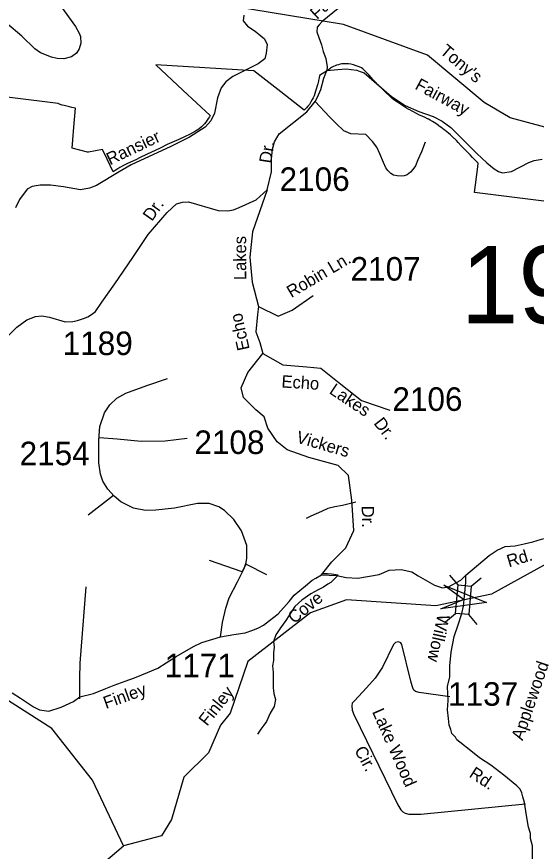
# Model space of a CAD drawing. Extents: x 884530 to 1028605, y 526725 to 653634.
# Drawn here: x 956415 to 959170, y 579851 to 584283 of the extents above; entities that cross this region are included whole.
import ezdxf

# ---------------------------------------------------------------- set-up
doc = ezdxf.new("R2010")
doc.units = 0
for name, color, linetype in [('Exist Boundary Political City Limit New', 7, 'Continuous'), ('Exist Hydrographic Creek Single Shore', 7, 'Continuous'), ('Exist Hydrographic Creek Single Shore Label', 7, 'Continuous'), ('Exist Hydrographic Misc Water Feature', 7, 'Continuous'), ('Exist Road Non-System Type 51', 7, 'Continuous'), ('Exist Road Non-System Type 51 Label', 7, 'Continuous'), ('Exist Road Secondary Structure Standard Bridge Attributed CELL', 7, 'Continuous'), ('Exist Road Secondary Structure Standard Bridge CELL', 7, 'Continuous'), ('Exist Road Secondary Structure Standard Bridge Number Label', 7, 'Continuous'), ('Exist Road Secondary Type 51 Attributed', 7, 'Continuous'), ('Exist Road Secondary Type 51 Label', 7, 'Continuous'), ('Exist Road Secondary Type 51 Number Label', 7, 'Continuous'), ('Map Preparation Boundary City Limit Buffer Line', 7, 'Continuous')]:
    doc.layers.add(name, color=color, linetype=linetype)

msp = doc.modelspace()

# ---------------------------------------------------------------- linework, layer by layer
at = {"layer": 'Exist Boundary Political City Limit New'}
for points in [[(958078.9, 584009.2), (958075.8, 584006.8), (958074.4, 584005.7), (958071.6, 584003.1), (958020.8, 583971.1), (958018.2, 583957.6), (958015.4, 583944.6), (958014.8, 583941.4), (958011.1, 583926.2), (957999.8, 583887.5), (957995.8, 583874.6), (957991.6, 583862.7), (957987.1, 583852.8), (957981.8, 583842.5), (957974.9, 583830.2), (957966.9, 583817.1), (957959.2, 583807.1), (957950.8, 583798.1), (957939, 583787.1), (957816.2, 583883.1), (957672.6, 583995.4), (957152.9, 584026.8), (957296.2, 583893.3), (957440.6, 583758.8), (957437.6, 583751.6), (957432.5, 583743.5), (957425.6, 583733.8), (957417.6, 583723.3), (957409.8, 583713.9), (957402.2, 583705.7), (957394.9, 583698.8), (957380.5, 583686.1), (957363.6, 583675.5), (957330.3, 583657.7), (957308.2, 583646.8), (957274.4, 583631.6), (957236.6, 583614.9), (957212.3, 583603.6), (957175.6, 583585.5), (957103.5, 583550.9), (957069.4, 583534.9), (957047.1, 583523.6), (957034.1, 583517.3), (956999.3, 583501.4), (956985.3, 583494.3), (956961.3, 583481.5), (956950.2, 583475.1), (956936.8, 583466.5), (956926.7, 583459.8), (956894, 583527), (956869.2, 583577.9), (956795.1, 583563.8), (956789.7, 583562.8), (956708.2, 583584.6), (956712.1, 583628.4), (956718, 583695.9), (956726.9, 583797.4), (956707.6, 583801.2), (956693.8, 583804.4), (956666.7, 583810.8), (956655.1, 583813.8), (956644.9, 583816.9), (956633.9, 583821.1), (955920.9, 583911.3)], [(958148.6, 584032.6), (958138.3, 584032), (958130.4, 584030.7), (958120.7, 584028.1), (958110, 584025), (958088.4, 584015.1), (958083.9, 584012.6), (958078.9, 584009.2)], [(961105.4, 583066.7), (958842.8, 583349.2), (958860.6, 583485.1), (958863, 583504.6), (958832.1, 583535.8), (958818.9, 583549.3), (958784.2, 583585.1), (958772.4, 583597.3), (958756.3, 583615), (958746.9, 583625), (958738.2, 583633.6), (958735.1, 583636.6), (958731.5, 583639.9), (958724, 583647.1), (958714.8, 583655.5), (958704.9, 583663.8), (958686.4, 583678.4), (958681.4, 583682.4), (958664.9, 583696.1), (958656.1, 583702.3), (958652.6, 583704.8), (958636.8, 583715.2), (958620.1, 583725.8), (958606.9, 583733.8), (958598.1, 583738.7), (958596.1, 583739.7), (958593.3, 583741.2), (958580.9, 583747.4), (958568.4, 583753.2), (958547.9, 583762.6), (958534.4, 583769.3), (958495.7, 583789.7), (958493.8, 583790.7), (958482.7, 583797.2), (958454.8, 583815.7), (958433.8, 583828.5), (958420.3, 583837.9), (958406.8, 583848.8), (958389.3, 583864.1), (958377.6, 583875.4), (958354.8, 583898.2), (958344, 583908.7), (958329.6, 583922.2), (958328.1, 583923.7), (958317.5, 583934.6), (958304.9, 583948.1), (958283.9, 583972), (958274.1, 583982.6), (958259, 583997.5), (958256.9, 583999.6), (958250.6, 584006.3), (958242.9, 584012.2), (958230.8, 584017.4), (958215.8, 584022.1), (958200.1, 584026.8), (958187.2, 584030.2), (958174.1, 584032.2), (958161.3, 584032.8), (958148.6, 584032.6)]]:
    msp.add_lwpolyline(points, dxfattribs=at)
at = {"layer": 'Exist Hydrographic Creek Single Shore'}
for points in [[(962595.4, 581173), (962571.5, 581284.8), (962503.2, 581512.8), (962414.3, 581897.2), (962368.7, 581972.4), (962207.5, 582192.9), (961744.5, 582879.2), (961617, 582987.1), (961505.9, 583064.7), (961336.7, 583108.1), (960713.9, 583186.3), (960566.8, 583274.5), (960148.7, 583287.6), (959704.9, 583646.6), (959288.3, 583677.7), (959032.2, 583745.2), (958893.2, 583826.8), (958593.5, 584078.9), (958148.8, 584242.1), (957369.3, 584369.4), (957205.1, 584441.6)], [(959310.4, 581426), (958932.1, 581217.6), (958637.9, 581154.6), (958163.4, 581186.7), (957973.4, 581117.9), (957639.8, 580859.1), (957546.9, 580585.3), (957494.7, 580520.7), (957431.2, 580374.3), (957301.6, 580245.7), (957235.4, 580020.6), (957182.4, 579933.1), (956980.5, 579881.3)]]:
    msp.add_lwpolyline(points, dxfattribs=at)
at = {"layer": 'Exist Hydrographic Misc Water Feature'}
for points in [[(956980.5, 579881.3), (956817.3, 580229.2), (956601.7, 580502.7), (956324.3, 580678.9), (956053.6, 581045.3), (955930.4, 581100.3)], [(956480.1, 579638.7), (956757, 579689), (956980.5, 579881.3)]]:
    msp.add_lwpolyline(points, dxfattribs=at)
at = {"layer": 'Exist Road Non-System Type 51'}
for p, q in [((956927.3, 581741.3), (956793.2, 581636.5)), ((957609.6, 581335.6), (957437, 581396.3)), ((957609.6, 581335.6), (957631.8, 581375.6)), ((957631.8, 581375.6), (957739, 581320.5))]:
    msp.add_line(p, q, dxfattribs=at)
for points in [[(956644, 584345.2), (956726.3, 584230.7), (956746.6, 584194.6), (956752.7, 584177.4), (956755.3, 584142.4), (956745.2, 584111.6), (956730.9, 584089.4), (956705, 584070.6), (956663.7, 584059.2), (956629.9, 584060), (956599.1, 584067.5), (956540, 584091.6), (956511.2, 584111.8), (956442, 584179.8), (956362.2, 584246.8), (956291.8, 584292.6)], [(958147.1, 584348.8), (958035.4, 584257.1), (958019.3, 584240.1), (958008.2, 584227.1), (958007.3, 584202.4), (958017.7, 584172.1), (958032, 584133), (958040.9, 584097.3), (958053.6, 584061.4), (958060.6, 584016.7), (958059.9, 583996.9)], [(958059.9, 583996.9), (958118.1, 584002.4), (958161.8, 584005.6), (958188.9, 584002.4), (958218.4, 583998.4), (958236.8, 583991.3), (958256.7, 583984.1), (958403.3, 583859.8), (958475.8, 583810.5), (958547, 583779.2), (958623.9, 583752.3), (958671.7, 583728.4), (958717.1, 583695), (958854.8, 583557), (958907.5, 583506.1), (958947.4, 583475.1), (958970.8, 583461.5), (958991.3, 583454.6), (959039.1, 583461.5), (959130.7, 583508.4), (959159.1, 583518.9), (959201.1, 583527.2)], [(958581.5, 583616.6), (958561.6, 583565.2), (958542.2, 583522), (958529.1, 583490.4), (958516.3, 583470.7), (958503.8, 583457.1), (958485.4, 583443.9), (958469.3, 583438.4), (958453.2, 583436.9), (958433.2, 583437.5), (958413.3, 583442.3), (958399.7, 583450.8), (958382.2, 583465.4), (958372.7, 583479.8), (958359.6, 583508.2), (958341.2, 583554.8), (958324.5, 583589.6), (958301.5, 583620.2), (958266.6, 583657.6), (958186.4, 583660.5), (958149.1, 583677.3), (958108.4, 583716), (958073.6, 583751.5), (957998, 583832.1)], [(956854.4, 582048.9), (956947.3, 582041.6), (957074.9, 582028.5), (957202.4, 582031.1), (957319.6, 582044.2)], [(958214.2, 581705.1), (958143, 581687.8), (958102.2, 581681.1), (958065.5, 581671.1), (958030.5, 581654.9), (957975, 581630.3), (957949.4, 581617.7)], [(958120.1, 581317.7), (958093, 581291.2), (958080.1, 581278.9), (958065.4, 581269.1), (958042, 581254.3), (958013, 581239.6), (957975.4, 581218), (957926.7, 581184.8), (957890.5, 581150.9), (957842.5, 581076.4), (957813, 581037.6), (957789.1, 581000.1), (957777.1, 580964.7), (957779.7, 580935.8), (957775.9, 580904.6), (957775.9, 580863.7), (957772, 580836.4), (957774, 580801.4), (957774, 580770.3), (957774, 580756.7), (957774, 580719.8), (957777.9, 580688.6), (957786.6, 580658.3), (957779.7, 580620), (957758.4, 580585.4), (957738.9, 580540.7), (957725.3, 580521.3), (957709.7, 580499.9), (957692.3, 580472.6)], [(958120.1, 581317.7), (958084.4, 581323.1), (958062.3, 581324.5), (958039.4, 581323.9)], [(956749.5, 580661.7), (956748.6, 580770.3), (956751, 580849.8), (956783.6, 581254.8)], [(958712.1, 580671.1), (958548.6, 580695), (958529, 580700.7), (958521.4, 580706.7), (958517.2, 580714.3), (958512.1, 580729.5), (958505.1, 580754.1), (958456.9, 580948.9), (958451.3, 580959.2), (958439.3, 580964.5), (958423.3, 580960.5), (958412.4, 580948.9), (958354.2, 580829.1), (958316.3, 580771.4), (958269.6, 580719.2), (958205.4, 580650.8), (958194.6, 580637.1), (958191.4, 580623.1), (958194.6, 580600.3), (958202, 580577.1), (958436.9, 580097.4), (958452.9, 580070.9), (958462.7, 580061.1), (958475.7, 580053.4), (958494.4, 580048), (958558.5, 580049.5), (959113.3, 580103.9)]]:
    msp.add_lwpolyline(points, dxfattribs=at)
at = {"layer": 'Exist Road Secondary Structure Standard Bridge Attributed CELL'}
msp.add_lwpolyline([(958680, 581264.6), (958905.8, 581172.7), (958664.3, 581139.3), (958784.9, 581187.9)], close=True, dxfattribs=at)
at = {"layer": 'Exist Road Secondary Structure Standard Bridge CELL'}
for p, q in [((958755.8, 581265.4), (958711.4, 581318.2)), ((958824.5, 581259.4), (958877.3, 581303.7)), ((958689.4, 581070.5), (958742.3, 581114.9)), ((958856.9, 581055.9), (958812.6, 581108.7))]:
    msp.add_line(p, q, dxfattribs=at)
msp.add_lwpolyline([(958742.3, 581114.9), (958755.4, 581265.4), (958825.7, 581259.3), (958812.6, 581108.7)], close=True, dxfattribs=at)
at = {"layer": 'Exist Road Secondary Type 51 Attributed'}
for points in [[(957618.9, 584291.5), (957616.6, 584261.3), (957639.4, 584232.8), (957678.7, 584205.5), (957709.7, 584182.1), (957729, 584165), (957743.2, 584135.4), (957738.4, 584089.9), (957730.4, 584058.6), (957695.7, 584032.9), (957561.7, 583964.6), (957523.6, 583937.8), (957498.6, 583904.8), (957479.9, 583852.5), (957463.3, 583771.5), (957445.1, 583730), (957414.4, 583696.8), (957330.4, 583642.8), (957231.4, 583594.4), (957021.7, 583495.9), (956957.7, 583458.9), (956837.2, 583386.3), (956800.9, 583372.3), (956753.7, 583363.2), (956662.9, 583380.3), (956593.5, 583388.8), (956538.3, 583388.8), (956497.3, 583380.9), (956470, 583366.6), (956428.9, 583312), (956407.7, 583267.5)], [(957742.8, 583363), (957765.8, 583458.5), (957766.3, 583528.6), (957770.9, 583579.6), (957781.8, 583617.9), (957806.3, 583661), (957953.4, 583778.3), (957998, 583832.1), (958009.2, 583856), (958027.5, 583896.8), (958044.4, 583956.6), (958059.9, 583996.9)], [(956333.6, 582553.8), (956414.9, 582635.2), (956468, 582674.1), (956513.9, 582691.8), (956547.7, 582694.6), (956588.1, 582688.3), (956672.4, 582663.2), (956711.8, 582664.8), (956737.1, 582670.4), (956768.1, 582680.2), (956792.7, 582689.4), (956811, 582701.3), (956832.1, 582716.8), (956866.5, 582766.8), (956935.8, 582864.9), (957031.2, 583004.6), (957112.2, 583126.9), (957212, 583243.6), (957263, 583289.2), (957294.8, 583298.8), (957325, 583299.4), (957482.3, 583253.5), (957535.1, 583252.1), (957563.9, 583257.7), (957594.8, 583269), (957684.4, 583309.9), (957742.8, 583363)], [(957742.8, 583363), (957666.1, 583141.3), (957651.7, 583006.3), (957663.2, 582874.1), (957697.7, 582744.9)], [(957697.7, 582744.9), (957801, 582693.2), (957875.6, 582724.8), (957987.6, 582802.3)], [(957697.7, 582744.9), (957691.9, 582701.8), (957683.3, 582609.9), (957703.4, 582552.4), (957720.9, 582493.7)], [(958031.5, 581319.2), (958085.4, 581387.8), (958160.1, 581462.5), (958203.1, 581554.4), (958191.6, 581715.3), (958174.4, 581847.4), (958119.9, 581899.1), (957964.9, 581942.2), (957850, 581982.4), (957795.5, 582025.5), (957746.7, 582097.3), (957726.6, 582157.7), (957683.6, 582195), (957617.5, 582261.1), (957606, 582312.8), (957640.5, 582393.2), (957720.9, 582493.7)], [(957720.9, 582493.7), (957826.8, 582434.6), (957953.1, 582423.2), (958027.8, 582417.4), (958134, 582331.2), (958243.1, 582245.1), (958394.3, 582193.3)], [(957495.7, 580989.5), (957506, 581066.4), (957524.7, 581141.6), (957541.8, 581198), (957586.2, 581282.8), (957621.5, 581352.9), (957632, 581384.8), (957634.8, 581408.7), (957634.8, 581475.3), (957607.2, 581552.8), (957566.3, 581612.6), (957517.6, 581660.4), (957486.3, 581679.8), (957436.2, 581698), (957373.6, 581698), (957251, 581673.6), (957152.3, 581662.1), (957097.1, 581660.4), (957034.5, 581672.9), (956967.6, 581707.1), (956931.2, 581736.7), (956897.1, 581774.3), (956872.3, 581816.5), (956859.8, 581854), (956851, 581913.3), (956849.6, 582034.6), (956854.8, 582107.7), (956880, 582180.4), (956907.9, 582221.4), (956946, 582257.2), (956993.5, 582283.4), (957105.1, 582324.4), (957215.2, 582362.6)], [(958796, 581318.2), (958919.8, 581421.4), (958962.8, 581449.9), (959005.6, 581470.4), (959058.8, 581473.1), (959105.3, 581483.5), (959152.4, 581494.3), (959198.9, 581508.8), (959263.1, 581524.9), (959361.5, 581563.7), (959486, 581597.9), (959613.4, 581635.6), (959728.8, 581667.3), (959899.6, 581719.1), (959986.9, 581739.1), (960039.3, 581757.9), (960070.3, 581765.7)], [(957495.7, 580989.5), (957565.7, 581003.2), (957626.5, 581012.2), (957667, 581025.7), (957697, 581037.7), (957724, 581052.7), (957756.2, 581077.5), (957801.4, 581112.1), (957859.8, 581177.2), (957886.4, 581211.8), (957946.2, 581261), (957982.1, 581290.2), (958002, 581302.2), (958031.5, 581319.2)], [(958031.5, 581319.2), (958113, 581315.6), (958162.2, 581304.9), (958223.3, 581300.9), (958337.6, 581320.9), (958390.7, 581343.5), (958453.2, 581347.5), (958510.3, 581335.5), (958544.8, 581314.2), (958629.9, 581265), (958673.7, 581250.4), (958704.3, 581255.7), (958770.7, 581291.6), (958796, 581318.2)], [(958788.8, 581188.3), (958793.3, 581243.8), (958797.3, 581279.7), (958796, 581318.2)], [(959150.9, 579795.6), (959150.9, 579880.3), (959140, 579918.7), (959139, 579946.7), (959130, 579979.1), (959118.1, 580041.6), (959108.5, 580110), (959099.5, 580140.4), (959094.3, 580162.5), (959084.9, 580180.9), (959083.1, 580182.9), (959067.6, 580199.4), (958997.6, 580255.9), (958929.2, 580308.2), (958868.6, 580348.5), (958822.5, 580385.1), (958764.3, 580431.1), (958749.5, 580444.1), (958741.3, 580457.2), (958722.2, 580476.4), (958716.8, 580498.5), (958708.2, 580521), (958705.4, 580557.1), (958698.7, 580602.7), (958702.5, 580652.6), (958700.5, 580687.4), (958698.9, 580726.6), (958712.1, 580777.4), (958712, 580836), (958718.5, 580907.9), (958734.8, 580991.1), (958756, 581053.2), (958775.9, 581114.6), (958783.9, 581153.1), (958788.8, 581188.3)], [(956390.8, 580692.6), (956434.3, 580664), (956467.3, 580643.8), (956504.4, 580618.4), (956536.3, 580601.8), (956584.3, 580595.8), (956650.2, 580616.8), (956716.2, 580646.8), (956749.2, 580670.8), (956821.2, 580688.8), (956887.2, 580715.8), (956932.2, 580733.8), (956990.7, 580754.1), (957040.2, 580772.1), (957107.7, 580800.6), (957163.1, 580824.6), (957206.6, 580851.6), (957260.6, 580886.1), (957305.6, 580913.1), (957352.1, 580938.6), (957397.1, 580959.6), (957495.7, 580989.5)]]:
    msp.add_lwpolyline(points, dxfattribs=at)
at = {"layer": 'Map Preparation Boundary City Limit Buffer Line'}
for points in [[(958078.9, 584009.2), (958075.8, 584006.8), (958074.4, 584005.7), (958071.6, 584003.1), (958020.8, 583971.1), (958018.2, 583957.6), (958015.4, 583944.6), (958014.8, 583941.4), (958011.1, 583926.2), (957999.8, 583887.5), (957995.8, 583874.6), (957991.6, 583862.7), (957987.1, 583852.8), (957981.8, 583842.5), (957974.9, 583830.2), (957966.9, 583817.1), (957959.2, 583807.1), (957950.8, 583798.1), (957939, 583787.1), (957816.2, 583883.1), (957672.6, 583995.4), (957152.9, 584026.8), (957296.2, 583893.3), (957440.6, 583758.8), (957437.6, 583751.6), (957432.5, 583743.5), (957425.6, 583733.8), (957417.6, 583723.3), (957409.8, 583713.9), (957402.2, 583705.7), (957394.9, 583698.8), (957380.5, 583686.1), (957363.6, 583675.5), (957330.3, 583657.7), (957308.2, 583646.8), (957274.4, 583631.6), (957236.6, 583614.9), (957212.3, 583603.6), (957175.6, 583585.5), (957103.5, 583550.9), (957069.4, 583534.9), (957047.1, 583523.6), (957034.1, 583517.3), (956999.3, 583501.4), (956985.3, 583494.3), (956961.3, 583481.5), (956950.2, 583475.1), (956936.8, 583466.5), (956926.7, 583459.8), (956894, 583527), (956869.2, 583577.9), (956795.1, 583563.8), (956789.7, 583562.8), (956708.2, 583584.6), (956712.1, 583628.4), (956718, 583695.9), (956726.9, 583797.4), (956707.6, 583801.2), (956693.8, 583804.4), (956666.7, 583810.8), (956655.1, 583813.8), (956644.9, 583816.9), (956633.9, 583821.1), (955920.9, 583911.3)], [(958148.6, 584032.6), (958138.3, 584032), (958130.4, 584030.7), (958120.7, 584028.1), (958110, 584025), (958088.4, 584015.1), (958083.9, 584012.6), (958078.9, 584009.2)], [(961105.4, 583066.7), (958842.8, 583349.2), (958860.6, 583485.1), (958863, 583504.6), (958832.1, 583535.8), (958818.9, 583549.3), (958784.2, 583585.1), (958772.4, 583597.3), (958756.3, 583615), (958746.9, 583625), (958738.2, 583633.6), (958735.1, 583636.6), (958731.5, 583639.9), (958724, 583647.1), (958714.8, 583655.5), (958704.9, 583663.8), (958686.4, 583678.4), (958681.4, 583682.4), (958664.9, 583696.1), (958656.1, 583702.3), (958652.6, 583704.8), (958636.8, 583715.2), (958620.1, 583725.8), (958606.9, 583733.8), (958598.1, 583738.7), (958596.1, 583739.7), (958593.3, 583741.2), (958580.9, 583747.4), (958568.4, 583753.2), (958547.9, 583762.6), (958534.4, 583769.3), (958495.7, 583789.7), (958493.8, 583790.7), (958482.7, 583797.2), (958454.8, 583815.7), (958433.8, 583828.5), (958420.3, 583837.9), (958406.8, 583848.8), (958389.3, 583864.1), (958377.6, 583875.4), (958354.8, 583898.2), (958344, 583908.7), (958329.6, 583922.2), (958328.1, 583923.7), (958317.5, 583934.6), (958304.9, 583948.1), (958283.9, 583972), (958274.1, 583982.6), (958259, 583997.5), (958256.9, 583999.6), (958250.6, 584006.3), (958242.9, 584012.2), (958230.8, 584017.4), (958215.8, 584022.1), (958200.1, 584026.8), (958187.2, 584030.2), (958174.1, 584032.2), (958161.3, 584032.8), (958148.6, 584032.6)]]:
    msp.add_lwpolyline(points, dxfattribs=at)

# ---------------------------------------------------------------- texts
at = {"layer": 'Exist Hydrographic Creek Single Shore Label'}
for s, rotation, p in [("Tony's", 319.9275, (958654.9, 584091.6)), ("Tony's", 319.9275, (958654.9, 584091.6)), ('Finley', 51.0416, (957424.5, 580512.2)), ('Finley', 51.0416, (957424.5, 580512.2))]:
    msp.add_text(s, height=65.62, rotation=rotation, dxfattribs=at).set_placement(p)
at = {"layer": 'Exist Road Non-System Type 51 Label'}
for s, rotation, p in [('Fairway', 42.9743, (958007.7, 584264.9)), ('Fairway', 331.5645, (958522.5, 583901.9)), ('Applewood', 71.1087, (959098, 580435.9)), ('Lake Wood', 293.8207, (958298.5, 580592.6)), ('Cir.', 298.5902, (958203.5, 580388.3))]:
    msp.add_text(s, height=65.62, rotation=rotation, dxfattribs=at).set_placement(p)
at = {"layer": 'Exist Road Secondary Structure Standard Bridge Number Label'}
msp.add_text('196', height=410.1, dxfattribs=at).set_placement((958770.9, 582655.5))
at = {"layer": 'Exist Road Secondary Type 51 Label'}
for s, rotation, p in [('Ransier', 25.413, (956909.6, 583493.6)), ('Dr.', 81.4733, (957764.6, 583501.6)), ('Dr.', 54.9226, (957131.9, 583192.8)), ('Lakes', 90.1196, (957631.9, 582884.3)), ('Robin Ln.', 30.7147, (957871.4, 582788.1)), ('Echo', 102.3573, (957650.8, 582518.1)), ('Echo', 356.3705, (957817.3, 582314.3)), ('Lakes', 326.4228, (958067.5, 582285.7)), ('Dr.', 307.5863, (958305.2, 582123.6)), ('Vickers', 343.9391, (957892.9, 582022.4)), ('Dr.', 270.7559, (958244.6, 581686.1)), ('Rd.', 16.5665, (959025.2, 581359)), ('Cove', 39.0618, (957885.9, 581056.7)), ('Willow', 257.2978, (958647.8, 581113.6)), ('Finley', 19.4852, (956887.7, 580606.9)), ('Rd.', 326.4226, (958809.6, 580249.8))]:
    msp.add_text(s, height=65.62, rotation=rotation, dxfattribs=at).set_placement(p)
at = {"layer": 'Exist Road Secondary Type 51 Number Label'}
for s, p in [('2106', (957808.9, 583357.8)), ('2107', (958185.4, 582881.6)), ('1189', (956658.4, 582486.3)), ('2106', (958407.1, 582189.9)), ('2108', (957357, 581960.9)), ('2154', (956430, 581901.3)), ('1171', (957199.8, 580775.7)), ('1137', (958702.5, 580624.4))]:
    msp.add_text(s, height=125, dxfattribs=at).set_placement(p)

doc.saveas('drawing.dxf')
